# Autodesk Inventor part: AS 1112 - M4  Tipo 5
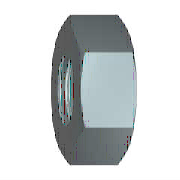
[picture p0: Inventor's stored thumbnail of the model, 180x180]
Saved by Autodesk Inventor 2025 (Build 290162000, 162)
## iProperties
Created: 2024-01
Part Number: AS 1112 - M4  Tipo 5
Material: Acciaio, Dolce
Description: Dadi esagonali metrici ISO, inclusi dadi sottili, dadi con intaglio e dadi a corona
Document SubType Name: Modeling
Standard: AS 1112
Designer: R5800u
Standards Organization: AS
Language: it-IT
Size Designation: M4  Tipo 5
Categories: <MemberInstance><Categories><Category DisplayName="Elementi di fissaggio" InternalName="e4da775c-781d-43d5-af7c-5136215cf5a6" Mnemonic="FSTN"><Category DisplayN
Density: 7.85 g/cm^3
Appearance: Semilucidato
IsCustomPart: 0
Author: R5800u
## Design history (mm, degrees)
workaxis "Work Axis1"
workplane "Work Plane1"
sketch "Schizzo1"
  geometry: L1 (-4.041, 0)-(-2.021, 3.5); L2 (-2.021, 3.5)-(2.021, 3.5); L3 (2.021, 3.5)-(4.041, 0); L4 (4.041, 0)-(2.021, -3.5); L5 (2.021, -3.5)-(-2.021, -3.5); L6 (-2.021, -3.5)-(-4.041, 0); 2 further points
  constraints: 12 end point, 1 coincident, 1 horizontal, 11 other
  dimensions: "d0" = 8.0829 distance of L3.end L1.start (= 1.1547 x SW)
extrude "Corpo" new body sketch "Schizzo1" distance "d1" = 3.2 (= KOH); taper "d2" = 0 deg
revolve "Smusso1" stored, may be unused: angle "d7" = 90 deg
sketch "Schizzo3"
  geometry: A1 r 3.5 centre (0, 0) between (-1.75, -3.031) and (1.75, -3.031) reference; 1 further point
  constraints: 1 coincident
hole "Filettatura" sketch "Schizzo3" diameter "d25" = 3.242; stored, may be unused: countersink angle "d29" = 82 deg, drill point angle "d31" = 118 deg; dims "d26" = 6, "d27" = 4, "d28" = 2, "d30" = 8
body "Solid1"
chamfer "Smusso2" distance "d8" = 0.37889 (= -0.5 x GD1 + 0.5 x NND); stored, may be unused: angle "d9" = 30 deg, second distance "d40" = 0.37889 (= -0.5 x GD1 + 0.5 x NND)
chamfer "Smusso3" distance "d10" = 0.37889 (= -0.5 x GD1 + 0.5 x NND); stored, may be unused: angle "d11" = 30 deg, second distance "d41" = 0.37889 (= -0.5 x GD1 + 0.5 x NND)
sketch "Schizzo2"
  geometry: L1 (0, 2.021)-(0, 4.041) reference; L2 (0, 4.041)-(3.2, 4.041) reference; L3 (3.2, 2.021)-(3.2, 4.041) reference; L4 (-0.64, 0)-(3.84, 0) reference; L5 (0.313, 4.041)-(0, 3.5); L6 (2.887, 4.041)-(3.2, 3.5)
  constraints: 4 end point, 4 point on line
  dimensions: "d3" = 30 deg angle of L1 L5 (= ANG1); "d4" = 30 deg angle of L3 L6 (= ANG2); "d5" = 7 diameter of L5.end L4 (= SW0); "d6" = 7 diameter of L6.end L4 (= SW01)
other parameters: "ANG1" = 30 deg [user parameter; used in 1 equation term], "ANG2" = 30 deg [user parameter; used in 1 equation term], "NND" = 4 [user parameter; used in 4 equation terms], "KOH" = 3.2 [user parameter; used in 1 equation term], "SW" = 7 [user parameter; used in 4 equation terms], "SW0" = 7 (= SW) [user parameter; used in 1 equation term], "SW01" = 7 (= SW) [user parameter; used in 1 equation term], "GD1" = 3.24223 (computed from THREADDIA, PTC, TOA) [user parameter; used in 4 equation terms], "d13" = 0, "d14" = 0, "d39" = 0, "d42" = 0, "GUL" = 0.37889 (= 0.541266 x PTC) [user parameter], "TPU" = 14.28571 (computed from PTC) [user parameter], "WFT" = 0.4 [user parameter], "THREADDIA" = 4 [user parameter; used in 1 equation term], "TOA" = 30 deg [user parameter; used in 1 equation term], "PTC" = 0.7 [user parameter; used in 4 equation terms], "E0" = 8.085 (= 1.155 x SW) [user parameter], "GAL" = 0.37889 (= 0.541266 x PTC) [user parameter]
